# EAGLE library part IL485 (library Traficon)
RS485 transceiver
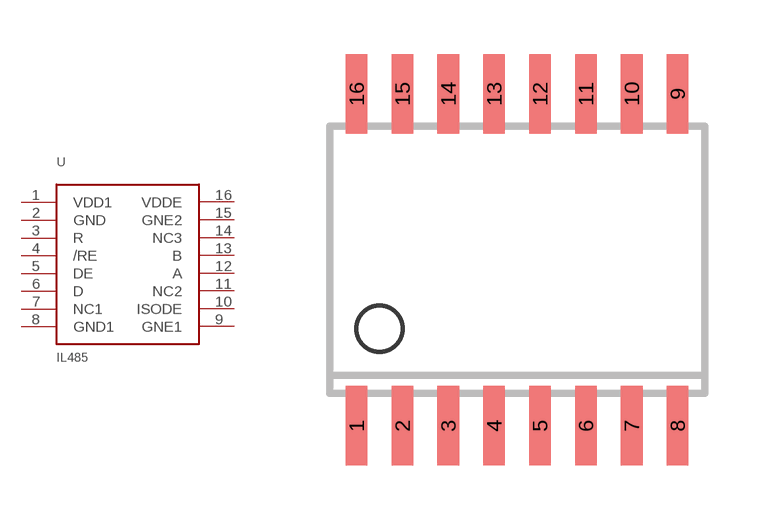
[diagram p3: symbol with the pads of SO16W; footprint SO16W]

Designator prefix -

## IL485  [SO16W]
1  VDD1  pas
2  GND  pas
3  R  out
4  /RE  in
5  DE  in
6  D  in
7  NC1  pas
8  GND1  pas
9  GNE1  pas
10  ISODE  pas
11  NC2  pas
12  A  out
13  B  out
14  NC3  pas
15  GNE2  pas
16  VDDE  pas

## Footprint SO16W (pad centres in mm)
SMALL OUTLINE INTEGRATED CIRCUIT wide body 7.5 mm/JEDEC MS-013AA
smd 0.6 x 2.2: 1 -4.445,-4.6; 2 -3.175,-4.6; 3 -1.905,-4.6; 4 -0.635,-4.6; 5 0.635,-4.6; 6 1.905,-4.6; 7 3.175,-4.6; 8 4.445,-4.6; 9 4.445,4.6; 10 3.175,4.6; 11 1.905,4.6; 12 0.635,4.6; 13 -0.635,4.6; 14 -1.905,4.6; 15 -3.175,4.6; 16 -4.445,4.6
